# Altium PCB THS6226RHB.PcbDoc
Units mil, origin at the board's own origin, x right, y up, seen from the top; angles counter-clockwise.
Board outline 1933 x 2970 mil, 4 copper layers (Top Layer, MidLayer1, MidLayer2, Bottom Layer); 77 components, 54 nets, 211 pads, 125 vias.
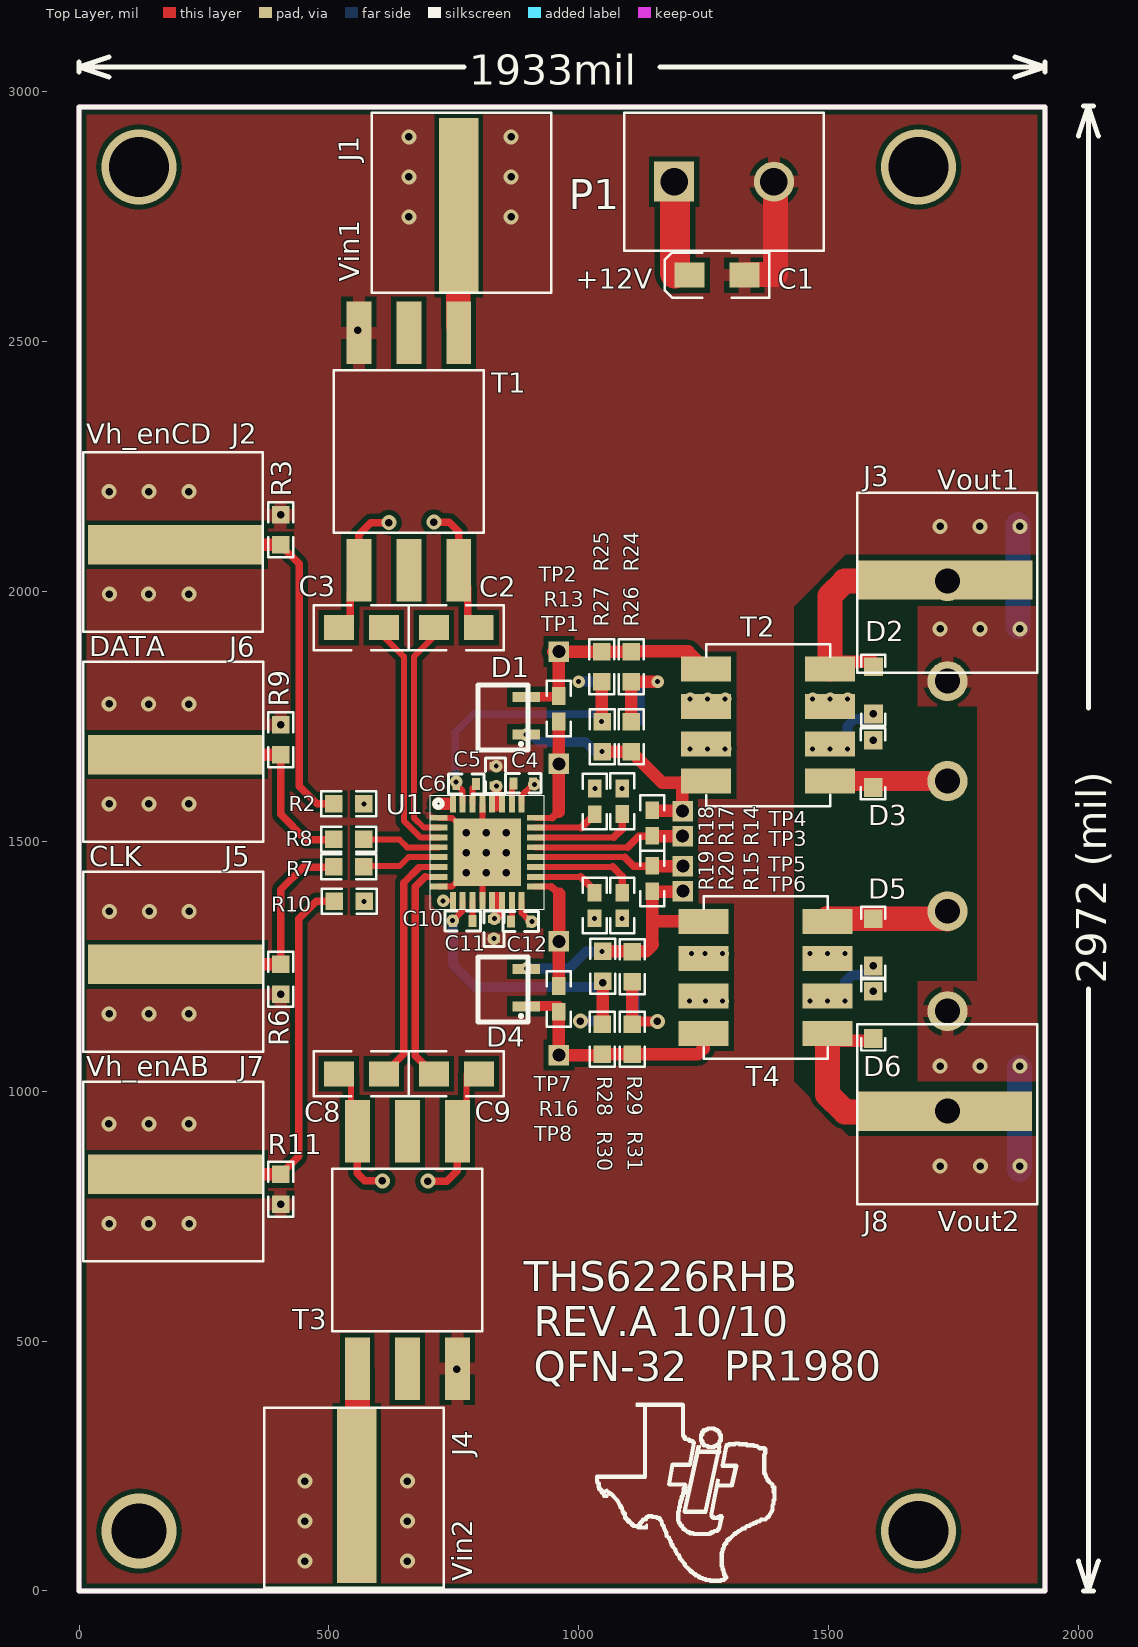
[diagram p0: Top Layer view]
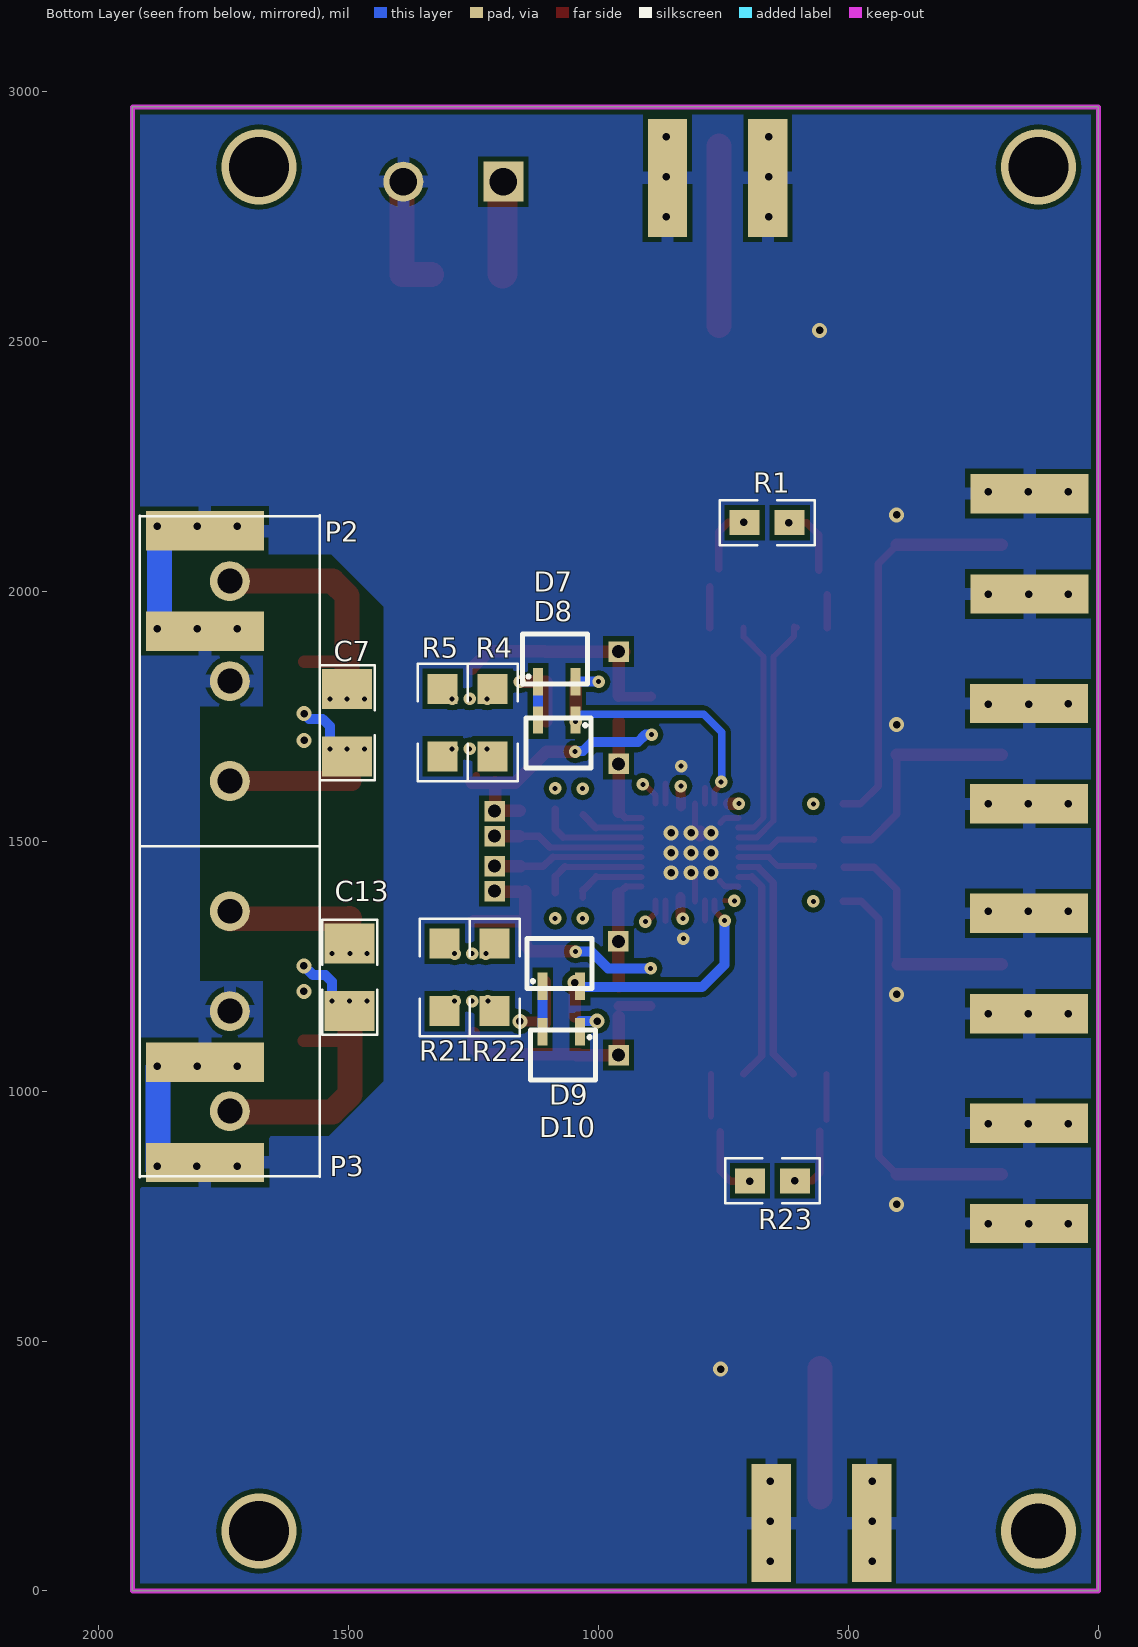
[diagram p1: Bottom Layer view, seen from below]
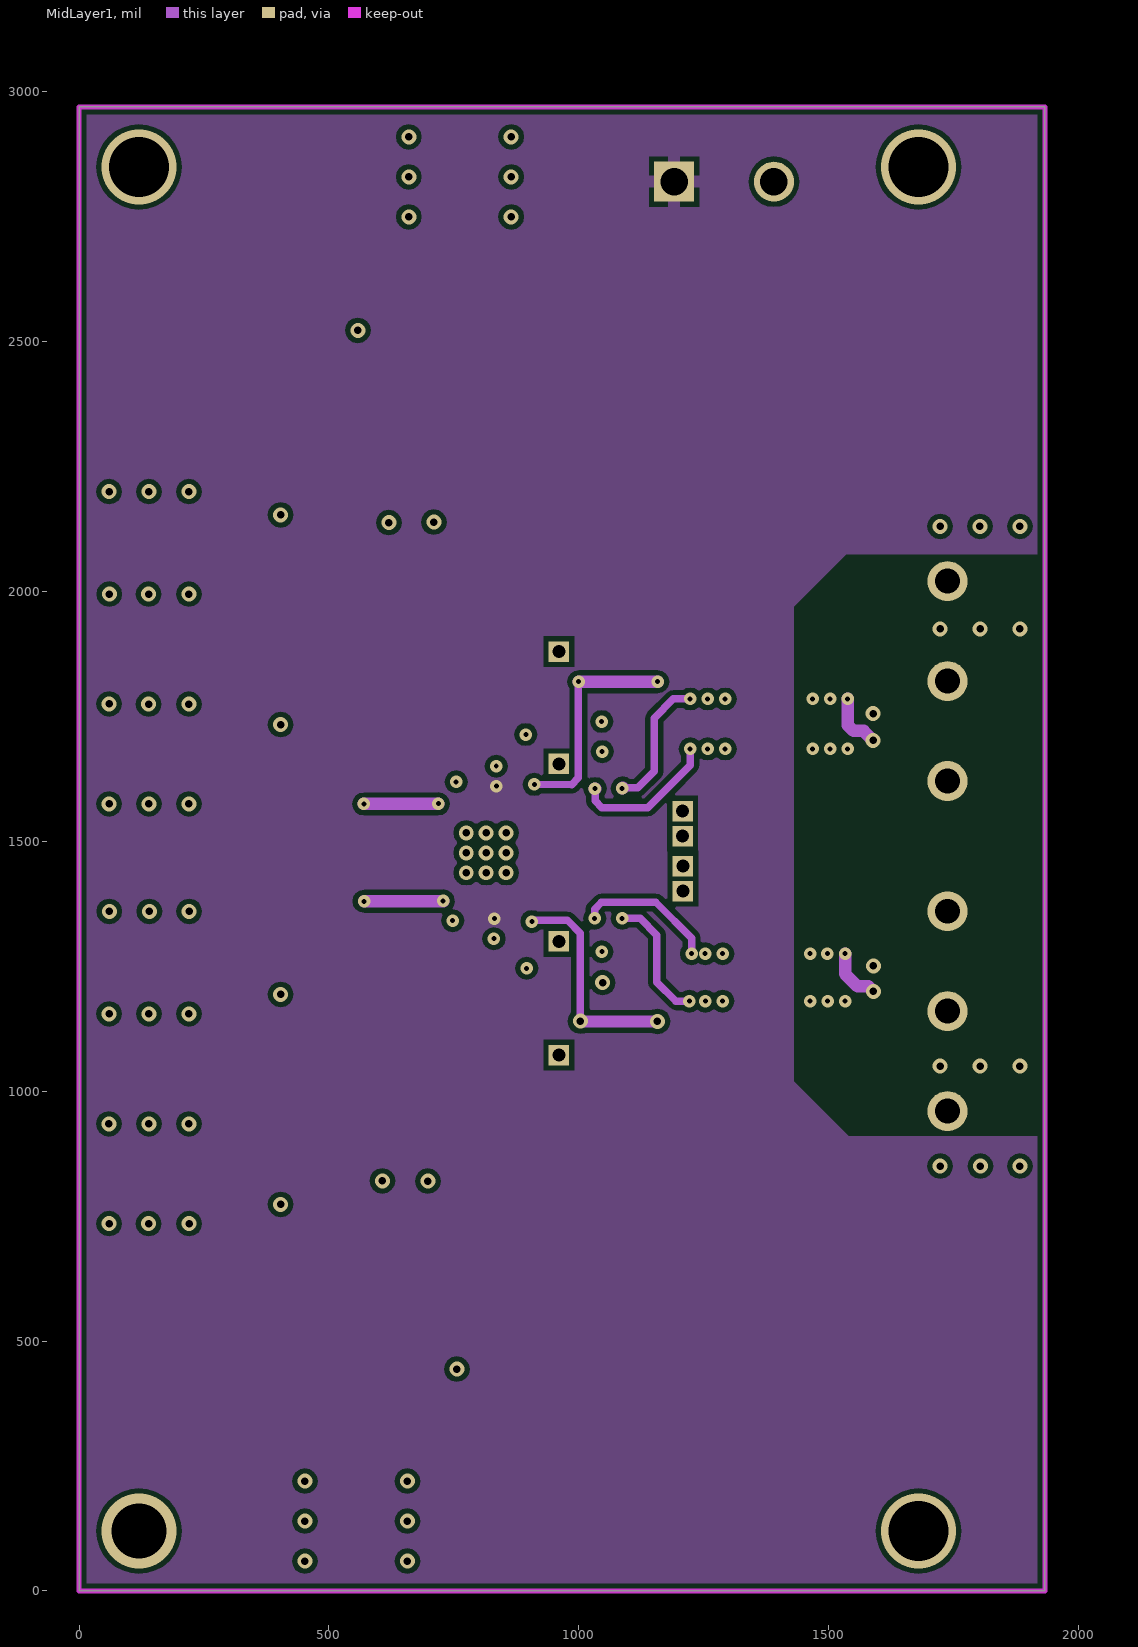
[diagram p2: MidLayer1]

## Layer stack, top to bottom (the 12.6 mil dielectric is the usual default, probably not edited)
Top Layer: signal copper 1.4
Dielectric: prepreg 12.6, FR-4, Dk 4.8
MidLayer1: signal copper 1.4
Dielectric: core 12.6, FR-4, Dk 4.8
MidLayer2: signal copper 1.4
Dielectric: prepreg 12.6, FR-4, Dk 4.8
Bottom Layer: signal copper 1.4

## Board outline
0,0 1933,0 1933,2970 0,2970

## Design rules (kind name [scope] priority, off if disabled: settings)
Clearance [All] p1: gap=5
ComponentClearance [All] p1: gap=10 collisioncheckmode=0 verticalgap=10
HoleSize [All] p1: absolutevalues=TRUE maxlimit=400 minlimit=0 maxpercent=80.000 minpercent=20.000
PlaneClearance [All] p1: clearance=30
PolygonConnect [All] p1: connectstyle=Relief reliefconductorwidth=25 reliefentries=4 polygonreliefangle="90 Angle"
RoutingLayers [All] p1: top layer_v5=TRUE mid layer 1_v5=FALSE mid layer 2_v5=FALSE bottom layer_v5=TRUE
RoutingVias [All] p1: holewidth=28 width=50 viastyle="Through Hole" minholewidth=28 minwidth=50 maxholewidth=28 maxwidth=50
ShortCircuit [All] p1 off: allowed=FALSE
SolderMaskExpansion [All] p1: expansion=5
TestPointUsage [All] p1: valid=0 allowmultiple=FALSE
Testpoint [All] p1: side=15 testpointundercomponent=TRUE minsize=40 maxsize=100 preferedsize=60 minholesize=0 maxholesize=40 preferedholesize=32 testpointgrid=1 style=1023 order=0123456789
Width [All] p1: maxlimit=1000 minlimit=10 preferedwidth=10 toplayer_prefwidth=25 midlayer1_prefwidth=15 bottomlayer_prefwidth=20 minimp=50.000000 maximp=50.000000 favimp=50.000000
13 further rules are at their usual default settings.

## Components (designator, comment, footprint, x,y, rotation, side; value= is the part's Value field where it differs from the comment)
C1 "2.2uF" 3216 1221.83,2633.47 r180 top (schematic designator C11)
C2 "4.7nF" 0805 710,1928 r0 top
C3 "4.7nF" 0805 520,1928 r0 top
C4 "1uF 16V" C402 869.38,1616.25 r0 top
C5 "100nF" C402 833.66,1651.59 r270 top
C6 "1uF 16V" C402 754.93,1614.92 r0 top
C7 "22nF" 1210 1503.22,1670.12 r90 bottom
C8 "4.7nF" 0805 610.13,1034.83 r180 top
C9 "4.7nF" 0805 800.13,1034.83 r180 top
C10 "1uF 16V" C402 787.74,1340.92 r180 top
C11 "100nF" C402 830.45,1305.58 r90 top
C12 "1uF 16V" C402 903.8,1339.96 r180 top
C13 "22nF" 1210 1498.31,1160.56 r90 bottom
D1 "AZ23C24-7-F" SOT23-2 894.87,1714.44 r90 top
D2 "CDSOD323-T12C" SOD-323 1590.2,1849.65 r270 top
D3 "CDSOD323-T12C" SOD-323 1589.44,1702.35 r270 top
D4 "AZ23C24-7-F" SOT23-2 894.87,1170.19 r90 top
D5 "CDSOD323-T12C" SOD-323 1589.82,1345.44 r270 top
D6 "CDSOD323-T12C" SOD-323 1589.82,1200.02 r270 top
D7 "ESDA14V2L" SOT23-2 1121.1,1819.44 r180 bottom
D8 "ESDA14V2L" SOT23-2 1046.32,1743.14 r0 bottom
D9 "ESDA14V2L" SOT23-2 1112.04,1209.84 r180 bottom
D10 "ESDA14V2L" SOT23-2 1037.63,1118.82 r0 bottom
J1 "Vin1" "SMA - SURFACE MOUNT" 760,2773 r270 top
J2 "VH_enCD" "SMA - SURFACE MOUNT" 193.22,2093.8 r0 top
J3 "Vout1" "SMA - SURFACE MOUNT" 1732.85,2023.21 r180 top
J4 "Vin2" "SMA - SURFACE MOUNT" 555.83,191.41 r90 top
J5 "CLK" "SMA - SURFACE MOUNT" 193.41,1254.01 r0 top
J6 "DATA" "SMA - SURFACE MOUNT" 193.41,1673.9 r0 top
J7 "VH_enAB" "SMA - SURFACE MOUNT" 193.41,833.93 r0 top
J8 "Vout2" "SMA - SURFACE MOUNT" 1732.48,960 r180 top
P1 "TERMINAL BLOCK 2" "TERM BLOCK 2 PINS 5MM" 1190.83,2820.47 r0 top
P2 "TERMINAL BLOCK 3" "TERMINAL BLOCK 3" 1738.14,2020.94 r270 bottom
P3 "TERMINAL BLOCK 3" "TERMINAL BLOCK 3 pins 5mm" 1738.14,960.38 r90 bottom
R1 "49.9W" 0805 708,2138 r180 bottom
R2 "0W" 0603 570.05,1575.07 r180 top
R3 "49.9W" 0603 403.55,2093.8 r90 top
R4 "20.4W  1%" 1206 1212.02,1670.5 r90 bottom
R5 "20.4W  1%" 1206 1312.48,1670.5 r90 bottom
R6 "49.9W" 0603 403.55,1193.92 r90 top
R7 "0W" 0603 570.05,1449.68 r180 top
R8 "0W" 0603 570.05,1504.82 r180 top
R9 "49.9W" 0603 403.55,1673.9 r90 top
R10 "0W" 0603 570.43,1380.18 r180 top
R11 "49.9W" 0603 403.55,833.93 r270 top
R13 "0W" 0402 960.21,1740.12 r90 top
R14 "0W" 0402 1147.44,1511.52 r90 top
R15 "0W" 0402 1147.35,1451.38 r270 top
R16 "0W" 0402 960.02,1210.6 r270 top
R17 "0W" 0402 1087.2,1606.13 r270 top
R18 "0W" 0402 1032.25,1605.95 r270 top
R19 "0W" 0402 1031.87,1346.09 r90 top
R20 "0W" 0402 1087.01,1346.09 r90 top
R21 "20.4W  1%" 1206 1308.14,1160.56 r90 bottom
R22 "20.4W  1%" 1206 1208.24,1160.56 r90 bottom
R23 "49.9W" 0805 607.13,820.83 r0 bottom
R24 "0W" 0603 1105.24,1880.06 r270 top
R25 "0W" 0603 1046.32,1820.01 r90 top
R26 "0W" 0603 1104.86,1680.07 r90 top
R27 "0W" 0603 1047.08,1739.94 r270 top
R28 "0W" 0603 1047.83,1280.1 r270 top
R29 "0W" 0603 1107.51,1219.66 r90 top
R30 "0W" 0603 1047.08,1073.87 r90 top
R31 "0W" 0603 1107.51,1134.31 r270 top
T1 "TT1-6-KK81" TT1-6-KK81 760,2518 r90 top (schematic designator T2)
T2 "BX4286LNL" BX4246_BX4286LNL 1503.22,1845.18 r0 top (schematic designator T1)
T3 "TT1-6_KK81" TT1-6-KK81 557.13,444.83 r270 top (schematic designator T4)
T4 "BX4286LNL" BX4246_BX4286LNL 1497.93,1340.34 r0 top (schematic designator T3)
TP1 "TEST POINT" TP1 960.21,1655.14 r0 top
TP2 "TEST POINT" TP1 960.21,1879.89 r0 top
TP3 "TEST POINT" TP1 1208.24,1510.68 r0 top
TP4 "TEST POINT" TP1 1208.24,1560.91 r0 top
TP5 "TEST POINT" TP1 1208.33,1450.53 r0 top
TP6 "TEST POINT" TP1 1208.33,1400.58 r0 top
TP7 "TEST POINT" TP1 960.58,1300.11 r0 top
TP8 "TEST POINT" TP1 960.21,1072.36 r0 top
U1 "THS6226RHB" "QFN 5.15X5.15 (32 PIN) RHB" 719.99,1547.44 r0 top

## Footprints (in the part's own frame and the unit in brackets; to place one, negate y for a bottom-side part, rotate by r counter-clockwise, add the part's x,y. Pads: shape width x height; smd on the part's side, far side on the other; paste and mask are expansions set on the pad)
0402 [mm]
  rect 0.9x0.7 smd: 1(0,0) 2(1.3,0)
  silkscreen extent -0.76,-0.61 2.06,0.61
0603 [mil]
  rect 35x35 smd: 1(0,0) 2(60,0)
  silkscreen extent -25,-25 85,25
0805 [mil]
  rect 60x50 smd: 1(0,0) 2(90,0)
  silkscreen extent -50,-45 140,45
1206 [mil]
  rect 60x60 smd: 1(0,0) 2(135,0)
  silkscreen extent -50,-50 185,50
1210 [mil]
  rect 80x100 smd: 1(0,0) 2(135,0)
  silkscreen extent -48,-55 182,55
3216 [mil]
  rect 60x50 smd: 1(0,0) 2(-110,0)
  silkscreen extent -160,-45 50,45
BX4246_BX4286LNL [mm] "VDSL Line Transformer"
  rect 2.54x1.27 smd: 1(0,0) 2(0,-1.9) 3(0,-3.8) 4(0,-5.7) 5(-6.3,-5.7) 6(-6.3,-3.8) 7(-6.3,-1.9) 8(-6.3,0)
  round 1.016 on Top Overlay: 1(1.269,1.265)
  silkscreen extent -6.3,-6.99 0.02,1.26
C402 [mm]
  rect 0.4x0.6 smd: 1(1,0) 2(0,0)
  silkscreen extent -0.4,-0.5 1.4,0.5
"QFN 5.15X5.15 (32 PIN) RHB" [mm]
  rect 0.87x0.3 smd: 1(0,0) 2(0,-0.5) 3(0,-1) 4(0,-1.5) 5(0,-2) 6(0,-2.5) 7(0,-3) 8(0,-3.5) 17(4.93,-3.5) 18(4.93,-3) 19(4.93,-2.5) 20(4.93,-2) 21(4.93,-1.5) 22(4.93,-1) 23(4.93,-0.5) 24(4.93,0)
  rect 0.3x0.87 smd: 9(0.715,-4.215) 10(1.215,-4.215) 11(1.715,-4.215) 12(2.215,-4.215) 13(2.715,-4.215) 14(3.215,-4.215) 15(3.715,-4.215) 16(4.215,-4.215) 25(4.215,0.715) 26(3.715,0.715) 27(3.215,0.715) 28(2.715,0.715) 29(2.215,0.715) 30(1.715,0.715) 31(1.215,0.715) 32(0.715,0.715)
  rect 3.45x3.45 smd: 33(2.465,-1.75)
  silkscreen extent -0.43,-4.65 5.37,1.15
"SMA - SURFACE MOUNT" [mm]
  rect 6x2 smd far side: 1(-1.4,2.6) 3(-1.4,-2.5)
  rect 8.9x2 smd: 2(0,0)
  silkscreen extent -4.7,-4.43 4.45,4.71
SOD-323 [mm]
  rect 0.95x0.95 smd: 1(0,0) 2(2.4,0)
  silkscreen extent -0.61,-0.62 3.01,0.6
SOT23-2 [mil]
  rect 20x55 smd: 1(0,0) 2(74.8,0)
  silkscreen extent -31,-4 99,96
"TERM BLOCK 2 PINS 5MM" [mil] "ED100/XDS"
  rect 80x80 hole 55: 1(0,0)
  round 80 hole 55: 2(200,0)
  silkscreen extent -100,-138 300,138
"TERMINAL BLOCK 3" [mil]
  round 80 hole 50: 1(0,0) 2(200,0) 3(400,0)
  silkscreen extent -132,-180 530,180
"TERMINAL BLOCK 3 pins 5mm" [mil] "ED100/XDS"
  round 80 hole 50: 1(0,0) 2(200,0) 3(400,0)
  silkscreen extent -132,-180 530,180
TP1 [mil]
  rect 41x41 hole 26: 1(0,0)
TT1-6-KK81 [mil] "RF Transformer SM"
  round 35 on Top Overlay: 0(-100.21,0.03)
  rect 125x50 smd: 1(-475,0) 2(-475,100) 3(-475,200) 4(0,200) 5(0,100) 6(0,0)
  silkscreen extent -400,-50 -75,250

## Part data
C1: library part "CAP (Polarized SM)"
C2 C3 C5 C8 C9 C11: library part CAP
C4 C6 C7 C10 C12 C13: library part "CAP (SM)"
D1 D7 D8 D9 D10: library part "SOT23 DBV_3PINS"
D2 D3 D5 D6: library part "SOD-323 (BIDIRECTIONAL)"
D4: library part "BAV99DW- QUAD"
J1 J2 J3 J4 J5 J7 J8: library part "SMA JACK"
J6: library part "CON (Jumper 3)"
P1: library part "TERMINAL BLOCK 3", "3 CONTACT TERMINAL BLOCK"
P2: library part "TERMINAL BLOCK 2", "2 CONTACT TERMINAL BLOCK"
P3: "3 CONTACT TERMINAL BLOCK"
R1 R2 R3 R4 R5 R6 R7 R8 R9 R10 R11 R13 R14 R15 R16 R17 R18 R19 R20 R21 R22 R23 R24 R25 R26 R27 R28 R29 R30 R31: library part "RES (SM)"
T2 T4: library part BX4120L
T3: library part TT1-6-KK81
U1: library part THS6204IPWP, "TSSOP-24"

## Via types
v1: diameter 30, hole 15, Top Layer to Bottom Layer, 74 vias
v2: diameter 25, hole 10, Top Layer to Bottom Layer, 47 vias
v3: diameter 150, hole 120, Top Layer to Bottom Layer, 3 vias
v4: diameter 150, hole 110, Top Layer to Bottom Layer, 1 vias

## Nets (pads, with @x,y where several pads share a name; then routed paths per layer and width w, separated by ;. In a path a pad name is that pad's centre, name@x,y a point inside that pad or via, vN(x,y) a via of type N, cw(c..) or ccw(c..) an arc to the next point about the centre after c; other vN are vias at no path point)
+12V: C1.1 C5.1 C11.1 P1.1 U1.13 U1.14 U1.27 U1.28 | length 262.1
  Top Layer w20: 835.36,1569.96 835.42,1575.51 835.42,1575.69 835.74,1610.96 C5.1@835.74,1611.53 ; C11.1@836.12,1349.05 836.27,1381.45 836.27,1381.54 836.31,1388.54
  Top Layer w60: C1.1@1192.83,2636.47 P1.1@1192.83,2817.47
  other v2: 831.48,1345.64 835.46,1610.96
GND: C1.2 C5.2 C11.2 J1.1 J1.3 J2.1 J2.3 J3.1 J3.3 J4.1 J4.3 J5.1 J5.3 J6.1 J6.3 J7.1 J7.3 J8.1 J8.3 P1.2 P2.2 P3.2 R3.2 R6.1 R9.2 R11.2 T1.4 T3.4 U1.1 U1.8 U1.12 U1.29 U1.33 | length 853.9
  Top Layer w12: U1.8 746.35,1409.64 U1.33@757.16,1420.45 ; U1.1 746.43,1547.31 U1.33@756.44,1537.49 ; U1.33@807.2,1517.44 U1.29 ; U1.12@807.4,1379.85 807.4,1381.49 U1.33@807.4,1435.79
  Top Layer w30: U1.33@796.99,1515.44 U1.33@796.99,1517.44
  Top Layer w50: C1.2@1334.83,2634.47 1393.83,2634.47 ; 1393.83,2635.47 1393.83,2820.47 P1.2@1393.83,2823.47
  Bottom Layer w50: J3.1@1878.76,1930.48 J3.3@1878.76,2134.81 ; J8.1@1881.78,843.86 J8.3@1881.78,1048.19
  other v1: 452.16,59.78 657.06,59.78 452.16,139.86 657.06,139.86 452.16,219.74 657.06,219.74 756.13,443.83 60.17,735.09 139.48,735.09 220.31,735.09 403.55,773.93 1723.41,850.47 1803.86,850.47 1883.17,850.47 59.79,934.88 139.86,934.88 219.93,934.88 1803.48,1050.27 1723.41,1050.65 1883.17,1050.65 60.17,1155.08 139.86,1155.08 219.93,1155.08 403.55,1193.92 60.54,1359.98 140.62,1359.98 220.5,1359.98 774.99,1437.44 814.99,1437.44 854.99,1437.44 774.99,1477.44 814.99,1477.44 854.99,1477.44 774.99,1517.44 814.99,1517.44 854.99,1517.44 60.17,1575.07 139.86,1575.07 219.93,1575.07 403.55,1733.9 60.17,1775.25 139.48,1774.87 219.93,1774.87 1723.41,1925.38 1883.17,1925.38 1803.29,1925.57 60.54,1995.07 139.48,1995.07 219.93,1995.07 1723.41,2130.47 1883.17,2130.47 1803.1,2130.85 403.55,2153.8 60.17,2200.15 139.86,2200.15 219.93,2200.15 558,2523 659.94,2750.07 865.03,2750.07 659.94,2829.95 865.03,2829.95 659.94,2910.03 865.03,2910.22
  other v2: 830.45,1305.58 835.04,1650.65
NetC2_1: C2.1 U1.2 | length 456.4
  Top Layer w12: C2.1 710,1909.72 670.14,1869.86 670.14,1547.88 689.97,1528.05 689.97,1527.86 719.99,1527.87 U1.2@721.51,1527.86
NetC2_2: C2.2 R1.1 T1.1 | length 213.9
  Top Layer w15: v1(710,2139) 741,2139 760.03,2119.89 T1.1@760,2046 ; C2.2@778,1928 T1.1@778,2010
NetC3_1: C3.1 R1.2 T1.3 | length 204.9
  Top Layer w15: C3.1@543,1928 T1.3@543,1994 ; T1.3 560,2114 584,2138 v1@618,2138
  other v1: 620,2138
NetC3_2: C3.2 U1.3 | length 490.2
  Top Layer w12: C3.2@603.48,1928 C3.2@603.48,1928.26 ; C3.2@608.95,1930.48 608.95,1911.03 650.03,1869.96 650.03,1541.17 682.98,1508.22 690.16,1508.22 U1.3
NetC4_2: C4.2 U1.26 | length 40.2
  Top Layer w12: U1.26 C4.2@866.25,1615.77
NetC6_1: C6.1 U1.30 | length 31.5
  Top Layer w12: U1.30 C6.1@787.51,1607.08
NetC7_1: C7.1 D2.2 T2.3 | length 108.5
  Bottom Layer w20: v2(1538.15,1685.23) 1538.15,1730.98 1552.2,1745.03 1579.62,1745.03 v1@1590.58,1755.99
  other v1: 1589.44,1755.99
  other v2: 1468.28,1685.23 1503.22,1685.23
NetC7_2: C7.2 D3.1 T2.2 | length 116.8
  MidLayer1 w25: v2(1538.15,1785.51) 1538.15,1751.76 1538.45,1751.46 1538.45,1732.95 1550.16,1721.24 1570.18,1721.24 1588.31,1703.11 v1@1590.2,1703.11
  other v1: 1589.44,1702.35
  other v2: 1503.22,1785.32 1468.28,1785.51
NetC8_1: C8.1 U1.6 | length 482
  Top Layer w12: 680.1,1447.6 680.1,1449.07 U1.6@718.89,1448.99
  Top Layer w15: C8.1 650.38,1075.08 650.38,1417.88 680.1,1447.6
NetC8_2: C8.2 R23.1 T3.1 | length 232.2
  Top Layer w12: T3.1@544.13,942.83 C8.2@544.13,1034.83
  Top Layer w15: T3.1 557.13,835.83 572.13,820.83 v1(607.13,820.83)
NetC9_1: C9.1 R23.2 T3.3 | length 225.7
  Top Layer w12: T3.3@775.13,949.83 C9.1@775.13,1034.83
  Top Layer w15: v1@703.13,819.83 736.13,819.83 757.13,840.83 T3.3@757.13,918.83
  other v1: 698.09,820.07
NetC9_2: C9.2 U1.7 | length 445.4
  Top Layer w12: 693.39,1429.33 U1.7 ; C9.2@709.19,1034.83 C9.2
  Top Layer w15: 693.39,1429.33 673.13,1409.07 673.13,1070.88 C9.2@709.19,1034.83
NetC10_2: C10.2 U1.11 | length 39.5
  Top Layer w12: C10.2@787.51,1342.02 U1.11
NetC12_1: C12.1 U1.15 | length 41
  Top Layer w12: C12.1@866.25,1340.46 U1.15
NetC13_1: C13.1 D5.2 T4.3 | length 113.1
  Bottom Layer w20: C13.1@1532.03,1183.4 C13.1@1533.54,1181.89 ; v2(1533.43,1180.57) 1533.43,1219.4 1546.54,1232.51 1571.31,1232.51 v1@1591.71,1252.9
  other v1: 1589.82,1250.95
  other v2: 1463.18,1180.57 1498.31,1180.57
NetC13_2: C13.2 D6.1 T4.2 | length 111.5
  MidLayer1 w25: v2(1533.43,1275.75) 1533.43,1235.26 1558.47,1210.22 1579.62,1210.22 v1(1589.82,1200.02)
  other v2: 1463.18,1275.75 1497.93,1275.75
NetD1_1: D1.1 R14.2 R26.1 R27.2 T2.5 TP4.1 | length 511.9
  Top Layer w15: T2.5@1244.5,1625.28 T2.5@1244.5,1631.22
  Top Layer w25: v2(1047.08,1679.94) 1104.73,1679.94 1166.91,1617.75 T2.5@1254.05,1617.75 ; R14.2@1158.38,1561.86 1207.29,1561.86 T2.5@1207.29,1618.44
  Bottom Layer w20: v2(894.11,1714.06) 906.58,1713.69 921.31,1698.96 1013.46,1698.96 1031.59,1680.83 v2@1048.21,1680.83
NetD1_2: D1.2 R13.2 R24.1 R25.2 T2.8 TP2.1 | length 476.4
  Top Layer w20: D1.2@894.87,1789.98 R13.2@960.21,1789.22
  Top Layer w25: TP2.1@948.88,1879.89 1106.77,1879.89 1107.51,1880.62 1219.31,1880.62 T2.8@1254.05,1845.88 ; TP2.1@959.45,1882.14 960.21,1881.38 R13.2
NetD2_1: D2.1 J3.2 P2.1 T2.1@1503.22,1845.18 | length 470.6
  Top Layer w25: T2.1@1512.39,1859.48 D2.1@1589.44,1859.48
  Top Layer w50: T2.1@1503.22,1845.18 1503.22,1991.78 1532.38,2020.94 P2.1
NetD3_2: D3.2 P2.3 T2.4 | length 249
  Top Layer w15: T2.4 T2.4@1504.1,1619.89
  Top Layer w40: T2.4@1494.15,1621.34 P2.3@1741.92,1621.34
NetD4_1: D4.1 R16.2 R30.1 R31.2 T4.5 TP8.1 | length 472
  Top Layer w20: D4.1@896.38,1170.56 R16.2@960.21,1170.56
  Top Layer w25: TP8.1@960.21,1070.1 R16.2@960.21,1148.84 ; TP8.1 R30.1@1044.06,1072.36 ; R30.1@1039.52,1073.87 1238.19,1073.87 1249.9,1085.58 T4.5
NetD4_2: D4.2 R15.2 R28.1 R29.2 T4.8 TP6.1 | length 531.4
  Top Layer w25: R28.1 1135.08,1280.1 1148.68,1294.07 ; R15.2@1146.79,1400.2 1147.16,1292.18 ; 1148.49,1340.34 T4.8 ; R15.2@1158.29,1399.35 TP6.1@1209.46,1399.35
  Bottom Layer w20: v2(896,1246.1) 981.36,1246.1 1014.6,1279.34 v2(1046.32,1279.34)
NetD5_1: D5.1 P3.3 T4.1@1497.93,1340.34 | length 239.7
  Top Layer w50: T4.1@1498.42,1345.44 P3.3@1738.14,1345.27
NetD6_2: D6.2 J8.2 P3.1 T4.4 | length 461.4
  Top Layer w25: T4.4@1500.62,1101 D6.2@1589.82,1101
  Top Layer w50: T4.4 1497.93,993.92 1532.79,959.06 J8.2@1733.72,959.06
NetD7_1: D7.1 D8.2 | length 79.7
  Bottom Layer w20: D8.2@1121.48,1741.63 D7.1@1121.48,1821.33
NetD9_1: D9.1 D10.2 | length 79.3
  Bottom Layer w20: D10.2@1112.06,1130.53 D9.1
NetJ1_2: J1.2 T1.6 | length 359
  Top Layer w50: T1.6@759,2533 759,2773 J1.2@759,2892.01
NetJ2_2: J2.2 R2.2 R3.1 | length 792.8
  Top Layer w15: R3.1@403.17,2093.8 R3.1@403.17,2095.69 ; R3.1@404.24,2092.13 440.5,2055.88 440.5,1610.95 476.38,1575.07 R2.2
  Top Layer w25: J2.2 R3.1
NetJ4_2: J4.2 T3.6 | length 257
  Top Layer w50: J4.2@557.13,187.83 557.13,191.41 T3.6
NetJ5_2: J5.2 R6.2 R7.2 | length 481.7
  Top Layer w15: R6.2 403.55,1403.87 448.52,1448.84 508.38,1448.84 R7.2@508.42,1448.79
  Top Layer w25: J5.2 R6.2@401.66,1254.01
NetJ6_2: J6.2 R8.2 R9.1 | length 455.6
  Top Layer w15: R9.1 403.55,1554.1 454,1503.64 R8.2@508.33,1503.64
  Top Layer w25: J6.2 R9.1
NetJ7_2: J7.2 R10.2 R11.1 | length 823.2
  Top Layer w15: R11.1@403.68,832.15 403.68,834.04 439.75,870.11 439.75,1345.06 474.87,1380.18 R10.2
  Top Layer w25: J7.2 R11.1
NetR2_1: R2.1 U1.32 | length 168.1
  Top Layer w25: v2(719.2,1575.78) 738.45,1575.78
  MidLayer1 w25: v2(570.05,1575.07) v2@718.86,1575.07
NetR4_1: R4.1 R5.1 R18.1 T2.6 | length 288.9
  MidLayer1 w15: v2@1033,1605.95 1033,1581.21 1046.32,1567.9 1138.48,1567.9 1223.16,1652.58 v2(1223.16,1685.23)
  MidLayer1 w25: v2(1032.25,1605.95) v2@1033,1605.95
  other v2: 1258.28,1685.23 1293.22,1685.23
NetR4_2: R4.2 R5.2 R17.1 T2.7 | length 272.6
  MidLayer1 w15: v2@1088.24,1607.18 1118.08,1607.18 1151.32,1640.41 1151.32,1746.92 1189.62,1785.22 v2(1223.25,1785.22)
  MidLayer1 w25: v2(1087.2,1606.13) v2@1088.24,1607.18
  other v2: 1258.19,1785.22 1293.22,1785.22
NetR7_1: R7.1 U1.5 | length 158.6
  Top Layer w12: R7.1@568.92,1450.43 569.3,1450.81 641.43,1450.81 659.32,1468.7 U1.5
NetR8_1: R8.1 U1.4 | length 159
  Top Layer w12: R8.1@569.04,1502.93 568.33,1503.64 641.39,1503.64 656.65,1488.38 U1.4
NetR10_1: R10.1 U1.9 | length 177.9
  Top Layer w10: v2(728.5,1381.36) U1.9
  MidLayer1 w25: v2(570.43,1380.18) v2@728.68,1380.18
NetR13_1: R13.1 TP1.1 U1.24 | length 231.3
  Top Layer w12: U1.24 946.93,1547.44
  Top Layer w15: 946.93,1547.44 960.21,1559.96
  Top Layer w25: 960.21,1559.96 R13.1
NetR14_1: R14.1 TP3.1 U1.21 | length 290.2
  Top Layer w12: U1.21 1098.25,1488.38
  Top Layer w15: 1098.25,1488.38 1120.35,1510.49 R14.1@1145.28,1510.49
  Top Layer w25: R14.1@1158.38,1510.68 TP3.1
NetR15_1: R15.1 TP5.1 U1.20 | length 291.8
  Top Layer w12: U1.20 1091.89,1468.7
  Top Layer w15: 1091.89,1468.7 1110.53,1450.06 R15.1@1146.03,1450.06
  Top Layer w25: R15.1@1157.25,1450.25 TP5.1@1209.37,1450.25
NetR16_1: R16.1 TP7.1 U1.17 | length 238.3
  Top Layer w12: U1.17 944.72,1409.64
  Top Layer w15: 944.72,1409.64 960.96,1395.67
  Top Layer w25: R16.1 TP7.1 ; TP7.1@960.96,1298.98 960.96,1395.67
NetR17_2: R17.2 U1.22 | length 216.6
  Top Layer w12: U1.22@915.64,1508.22 1070.49,1508.22
  Top Layer w15: 1070.49,1508.22 1087.2,1524.93 R17.2 ; R17.2@1087.2,1564.77 R17.2@1087.26,1556.66
NetR18_2: R18.2 U1.23 | length 127.8
  Top Layer w12: U1.23 1005.42,1527.75
  Top Layer w15: 1005.42,1527.75 R18.2@1031.21,1553.54
NetR19_1: R19.1 R21.2 R22.2 T4.7 | length 278.5
  MidLayer1 w15: v2(1031.87,1346.09) 1031.87,1364.22 1045.57,1377.92 1154.72,1377.92 1225.9,1306.74 v2(1225.9,1275.56)
  other v2: 1253.18,1275.56 1288.31,1275.56
NetR19_2: R19.2 U1.18 | length 146.5
  Top Layer w12: U1.18 1004.35,1429.33
  Top Layer w13: R19.2@1031.87,1387.08 R19.2@1031.87,1404.38
  Top Layer w15: 1004.35,1429.33 R19.2@1031.87,1401.81
NetR20_1: R20.1 R21.1 R22.1 T4.6 | length 258.3
  MidLayer1 w15: v2(1087.01,1346.09) 1123.09,1346.09 1156.61,1312.58 1156.61,1218.53 1194.75,1180.38 v2(1221.57,1180.38)
  other v2: 1253.37,1180.57 1288.31,1180.57
NetR20_2: R20.2 U1.19 | length 213.5
  Top Layer w12: U1.19 1067.94,1449.01
  Top Layer w15: 1067.94,1449.01 1087.01,1429.94 R20.2
VHH_AB: C10.1 D9.2 R28.2 R30.2 U1.10 | length 510.6
  Top Layer w12: v2(747.94,1341.66) 767.83,1361.54 U1.10
  Top Layer w25: R30.2@1047.83,1150.49 R28.2
  Bottom Layer w20: v2@748.37,1340.92 748.37,1253.23 793.27,1208.33 D9.2@1034.99,1208.33
  other v1: 1047.83,1217.4
VHH_CD: C4.1 D7.2 R24.2 R26.2 U1.25 | length 666.4
  Top Layer w12: U1.25 885.94,1592.21 C4.1@905.82,1612.09
  Top Layer w25: R26.2@1105.24,1740.45 R24.2 ; R24.2@1105.48,1819.82 v2(1158.12,1819.82)
  MidLayer1 w15: v2(911.3,1614.16) 986.08,1613.98 999.49,1627.38 v2@999.49,1821.71
  MidLayer1 w25: v2(999.87,1819.82) v2(1158.12,1819.82)
  Bottom Layer w20: v2(999.87,1819.82) D7.2@1042.92,1819.82
VLL_AB: C12.2 D10.1 R29.1 R31.1 U1.16 | length 648
  Top Layer w12: U1.16 885.94,1357.01 C12.2@902.42,1340.53
  Top Layer w20: R31.1@1112.42,1139.97 v1(1157.74,1139.97)
  Top Layer w25: R31.1@1107.51,1135.82 R29.1
  MidLayer1 w15: v2@905.82,1342.04 977.58,1342.04 1003.27,1316.35 v1(1003.27,1140.35)
  MidLayer1 w25: v1@1004.4,1139.59 v1(1157.74,1139.97)
  Bottom Layer w20: v1(1003.27,1140.35) D10.1@1036.88,1140.35
  other v2: 906.58,1339.77
VLL_CD: C6.2 D8.1 R25.1 R27.1 U1.31 | length 517.6
  Top Layer w12: C6.2 754.97,1614.88 767.77,1601.51 U1.31
  Top Layer w25: R27.1@1046.32,1740.31 R25.1
  Bottom Layer w15: v2@753.23,1620.02 753.23,1718.22 789.49,1754.48 1033.48,1754.48
  other v2: 754.74,1619.26 1046.13,1740.12
pads on no net: T1.0 T1.2 T1.5 T2.1@1553.16,1894.99 T3.0 T3.2 T3.5 T4.1@1547.87,1390.14
copper on no net:
  other v3: 1680,120 120,2850 1680,2850
  other v4: 120,120

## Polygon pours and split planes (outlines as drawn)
GND on Top Layer (solid, remove dead copper): 0.21,0.19 1932.95,0.19 1932.95,910.05 1540.25,910.05 1430.34,1019.96 1430.34,1970.23 1534.96,2074.85 1933.43,2074.85 1933.43,2969.98 0.02,2969.98 0.02,-0.19
GND on Top Layer (solid, remove dead copper): 1928.31,1970.56 1678.47,1970.56 1678.47,1770.53 1797.82,1770.53 1797.82,1220.61 1678.47,1220.61 1678.47,1020.62 1928.31,1020.62
+12V on MidLayer1 (solid, remove dead copper): 0.3,0.1 1933.05,0.1 1933.05,909.96 1540.34,909.96 1430.43,1019.87 1430.43,1970.14 1535.06,2074.76 1933.52,2074.76 1933.52,2969.89 0.11,2969.89 0.11,-0.28
GND on Bottom Layer (solid, remove dead copper): 0.3,0.1 1933.05,0.1 1933.05,909.96 1540.34,909.96 1430.43,1019.87 1430.43,1970.14 1535.06,2074.76 1933.52,2074.76 1933.52,2969.89 0.11,2969.89 0.11,-0.28
GND on Bottom Layer (solid, remove dead copper): 1936.51,1970.54 1672.31,1970.54 1672.31,1770.5 1798.52,1770.5 1798.52,1220.58 1672.31,1220.58 1672.31,1020.59 1936.51,1020.59

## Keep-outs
Keep-Out Layer:
  the board outline again, w10

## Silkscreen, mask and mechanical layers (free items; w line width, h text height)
Top Overlay:
  drawing of 1188 lines, arcs and shapes, not listed
  text "1933mil" at 780.56,3014.01 h60
  text "Vin1" at 560.61,2620.15 h40 r90
  text "+12V" at 994.2,2605.8 h40
  text "Vh_enCD" at 14.89,2295.53 h40
  text "Vout1" at 1718.09,2203.61 h40
  text "DATA" at 20.03,1870.28 h40
  text "CLK" at 20.03,1450.17 h40
  text "2972 (mil)" at 2055.99,1215.09 h60 r90
  text "Vh_enAB" at 14.89,1029.69 h40
  text "Vout2" at 1718.5,720.17 h40
  text "THS6226RHB" at 889.58,599.87 h60
  text "REV.A 10/10" at 909.98,509.98 h60
  text "PR1980" at 1291.07,421.22 h60
  text "QFN-32" at 909.98,420.09 h60
  text "Vin2" at 786.98,19.94 h40 r90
